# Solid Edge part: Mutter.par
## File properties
Sűrűség: 0,000 kg/m^3
Pontosság: 0,990
Author: bmolnar
Last saved by: bmolnar
Revision: 76
Username: bmolnar
Dokumentum tartalom típus: 0
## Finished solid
Body 1: solid body, 23 faces, 46 edges, 24 vertices.
  Faces by surface: cone 14, plane 8, cylinder 1
  Edges by curve: spline 24, circle 16, line 6
Bounding box of the edges (mm): 6.000 x 19.630 x 17.000, from (0, -9.815, -8.5) to (6, 9.815, 8.5).
Cylindrical faces by radius (mm): R4.3235 x1
Conical faces (half-angle, radius in mm at the cone's reference point): 60 deg R4.6618 x2, 60 deg R9.1575 x12
Planar faces by outward normal: +x 1, +z 1, -x 1, -z 1, oblique 4
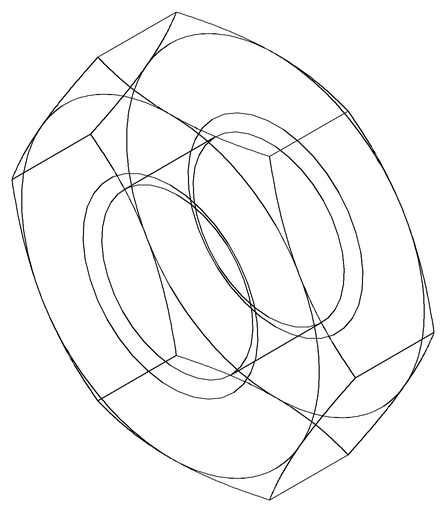
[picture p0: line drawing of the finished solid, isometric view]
